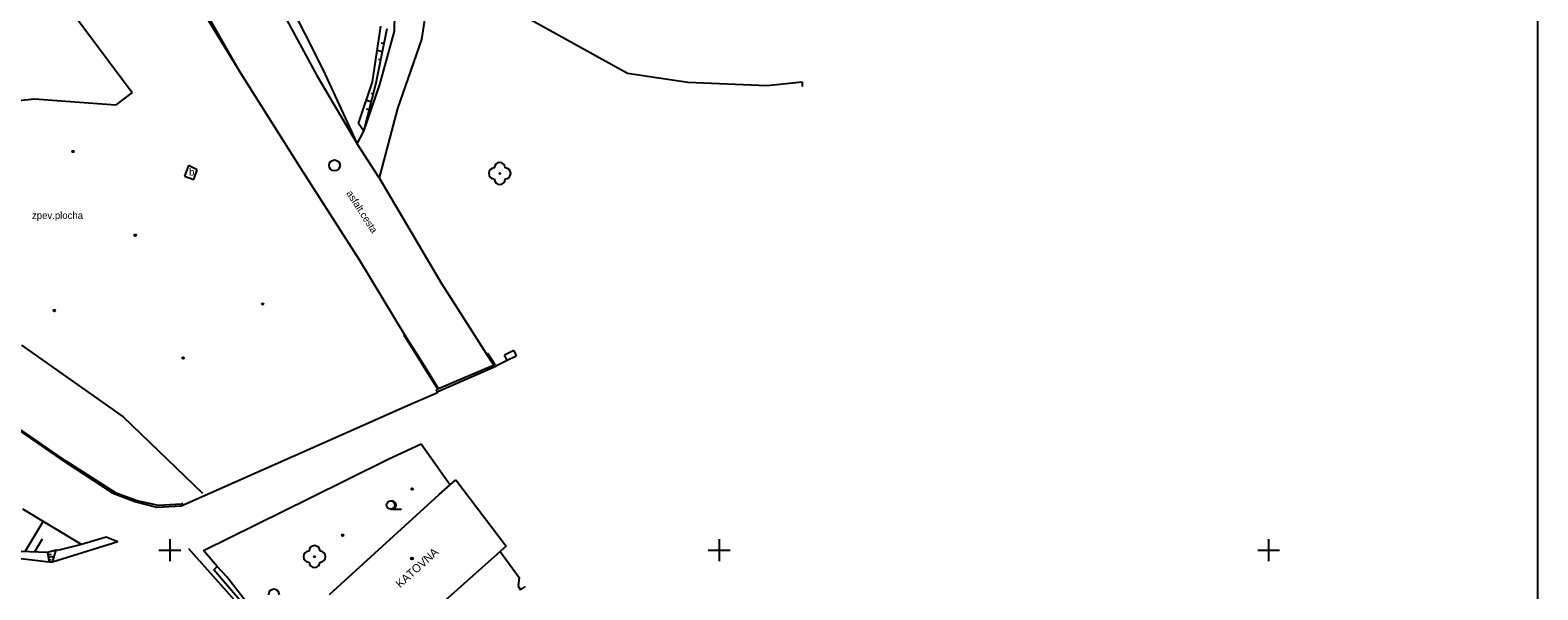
# Model space of a CAD drawing. Extents: x -639440 to -639026, y -1138850 to -1138262.
# Drawn here: x -639162.7 to -639025.5, y -1138653.6 to -1138602.7 of the extents above; entities that cross this region are included whole.
import ezdxf

# ---------------------------------------------------------------- set-up
doc = ezdxf.new("R2010")
doc.units = 0
for name, color, linetype in [('Vrstva 10', 7, 'Continuous'), ('Vrstva 11', 7, 'Continuous'), ('Vrstva 14', 7, 'Continuous'), ('Vrstva 15', 7, 'Continuous'), ('Vrstva 20', 7, 'Continuous'), ('Vrstva 22', 7, 'Continuous'), ('Vrstva 23', 7, 'Continuous'), ('Vrstva 27', 7, 'Continuous'), ('Vrstva 36', 7, 'Continuous'), ('Vrstva 39', 7, 'Continuous'), ('Vrstva 40', 7, 'Continuous'), ('Vrstva 41', 7, 'Continuous'), ('Vrstva 5', 7, 'Continuous'), ('Vrstva 60', 7, 'Continuous'), ('Vrstva 61', 7, 'Continuous'), ('Vrstva 7', 7, 'Continuous'), ('Vrstva 8', 7, 'Continuous')]:
    doc.layers.add(name, color=color, linetype=linetype)

msp = doc.modelspace()

# ---------------------------------------------------------------- linework, layer by layer
at = {"layer": 'Vrstva 10'}
for p, q in [((-639142.24, -1138596.43), (-639136.62, -1138606.78)), ((-639143.51, -1138606.64), (-639148.48, -1138597.96)), ((-639129.57, -1138602.75), (-639129.5, -1138599.47)), ((-639126.56, -1138599.96), (-639127.11, -1138603.5)), ((-639130.89, -1138607.61), (-639129.57, -1138602.75)), ((-639127.11, -1138603.5), (-639129.3, -1138609.79)), ((-639138.11, -1138615.21), (-639143.51, -1138606.64)), ((-639136.62, -1138606.78), (-639132.96, -1138613.01)), ((-639132.36, -1138611.87), (-639130.89, -1138607.61)), ((-639129.3, -1138609.79), (-639130.97, -1138616.1)), ((-639132.96, -1138613.01), (-639132.36, -1138611.87)), ((-639130.97, -1138616.1), (-639132.96, -1138613.01)), ((-639132.73, -1138623.64), (-639138.11, -1138615.21)), ((-639130.97, -1138616.1), (-639125.29, -1138625.72)), ((-639128.64, -1138630.36), (-639132.73, -1138623.64)), ((-639125.29, -1138625.72), (-639124.25, -1138627.32)), ((-639124.25, -1138627.32), (-639121.21, -1138632.1)), ((-639126.66, -1138633.52), (-639128.64, -1138630.36)), ((-639121.21, -1138632.1), (-639120.63, -1138632.97)), ((-639125.55, -1138635.32), (-639126.66, -1138633.52)), ((-639120.5, -1138633.16), (-639125.55, -1138635.32)), ((-639120.63, -1138632.97), (-639120.5, -1138633.16)), ((-639154.75, -1138649.25), (-639155.79, -1138648.83))]:
    msp.add_line(p, q, dxfattribs=at)
at = {"layer": 'Vrstva 11'}
for p, q in [((-639162, -1138596.86), (-639153.43, -1138608.35)), ((-639092.46, -1138607.38), (-639092.47, -1138607.8)), ((-639162.32, -1138608.96), (-639167.4, -1138609.48)), ((-639154.94, -1138609.49), (-639162.32, -1138608.96)), ((-639153.43, -1138608.35), (-639154.94, -1138609.49)), ((-639148.3, -1138614.99), (-639148.67, -1138615.95)), ((-639147.52, -1138615.37), (-639148.3, -1138614.99)), ((-639148.67, -1138615.95), (-639147.84, -1138616.25)), ((-639147.84, -1138616.25), (-639147.52, -1138615.37)), ((-639163.51, -1138631.34), (-639154.27, -1138637.86)), ((-639128.64, -1138630.36), (-639128.71, -1138630.41)), ((-639128.71, -1138630.41), (-639127.1, -1138632.97)), ((-639121.21, -1138632.1), (-639121.09, -1138632.06)), ((-639121.09, -1138632.06), (-639120.44, -1138633.09)), ((-639127.1, -1138632.97), (-639125.64, -1138635.32)), ((-639120.44, -1138633.09), (-639120.5, -1138633.16)), ((-639125.64, -1138635.32), (-639125.55, -1138635.32)), ((-639154.27, -1138637.86), (-639147.04, -1138644.82)), ((-639154.75, -1138649.25), (-639160.68, -1138651.1)), ((-639155.79, -1138648.83), (-639158.06, -1138649.5)), ((-639161, -1138651.09), (-639165.14, -1138650.62)), ((-639158.06, -1138649.5), (-639160.23, -1138650.04)), ((-639160.68, -1138651.1), (-639161, -1138651.09)), ((-639144.83, -1138652.44), (-639145.69, -1138651.48)), ((-639142.65, -1138655.24), (-639144.83, -1138652.44))]:
    msp.add_line(p, q, dxfattribs=at)
at = {"layer": 'Vrstva 14'}
for p, q in [((-639143.51, -1138606.64), (-639147.06, -1138600.83)), ((-639131.57, -1138607.38), (-639130.82, -1138602.31)), ((-639131.22, -1138607.47), (-639130.23, -1138602.51)), ((-639117.74, -1138601.4), (-639108.34, -1138606.57)), ((-639108.34, -1138606.57), (-639102.87, -1138607.4)), ((-639132.84, -1138611.17), (-639131.57, -1138607.38)), ((-639132.36, -1138611.87), (-639131.22, -1138607.47)), ((-639102.87, -1138607.4), (-639095.68, -1138607.7)), ((-639095.68, -1138607.7), (-639092.46, -1138607.38)), ((-639132.36, -1138611.87), (-639132.84, -1138611.17)), ((-639158.06, -1138649.5), (-639163.4, -1138646.27)), ((-639161.13, -1138650.22), (-639165.18, -1138650.05)), ((-639160.34, -1138650.01), (-639161.13, -1138650.22)), ((-639161.13, -1138650.22), (-639161, -1138651.09)), ((-639160.68, -1138651.1), (-639160.34, -1138650.01)), ((-639160.23, -1138650.04), (-639160.34, -1138650.01)), ((-639145.11, -1138652.81), (-639146, -1138651.8)), ((-639142.43, -1138655.97), (-639145.11, -1138652.81))]:
    msp.add_line(p, q, dxfattribs=at)
at = {"layer": 'Vrstva 15'}
for p, q in [((-639130.51, -1138603.89), (-639130.77, -1138603.84)), ((-639130.65, -1138604.63), (-639131.15, -1138604.53)), ((-639130.8, -1138605.36), (-639131.03, -1138605.32)), ((-639131.67, -1138609.2), (-639132.14, -1138609.08)), ((-639131.48, -1138608.48), (-639131.69, -1138608.42)), ((-639131.86, -1138609.93), (-639132.12, -1138609.86)), ((-639163.18, -1138650.13), (-639161.53, -1138647.4)), ((-639162.32, -1138650.17), (-639161.6, -1138648.98)), ((-639161.1, -1138650.42), (-639160.77, -1138650.37)), ((-639161.07, -1138650.65), (-639160.51, -1138650.56)), ((-639161.03, -1138650.87), (-639160.81, -1138650.84))]:
    msp.add_line(p, q, dxfattribs=at)
at = {"layer": 'Vrstva 20'}
for centre, radius in [((-639158.82, -1138613.71), 0.075), ((-639158.82, -1138613.71), 0.0204), ((-639153.16, -1138621.33), 0.075), ((-639153.16, -1138621.33), 0.0204), ((-639160.52, -1138628.19), 0.075), ((-639160.52, -1138628.19), 0.0204), ((-639141.56, -1138627.6), 0.075), ((-639141.56, -1138627.6), 0.0204), ((-639148.8, -1138632.51), 0.075), ((-639148.8, -1138632.51), 0.0204), ((-639127.95, -1138644.43), 0.075), ((-639127.95, -1138644.43), 0.0204), ((-639134.28, -1138648.64), 0.075), ((-639134.28, -1138648.64), 0.0204)]:
    msp.add_circle(centre, radius, dxfattribs=at)
at = {"layer": 'Vrstva 22'}
for centre in [(-639119.98, -1138615.71), (-639136.84, -1138650.59)]:
    msp.add_circle(centre, 0.05, dxfattribs=at)
for centre, start, end in [((-639119.98, -1138615.21), 0, 180), ((-639120.48, -1138615.71), 90, 270), ((-639119.98, -1138616.21), 180, 0), ((-639119.48, -1138615.71), 270, 90), ((-639137.34, -1138650.59), 90, 270), ((-639136.84, -1138650.09), 0, 180), ((-639136.34, -1138650.59), 270, 90), ((-639136.84, -1138651.09), 180, 0), ((-639140.54, -1138654.06), 0, 180)]:
    msp.add_arc(centre, 0.5, start, end, dxfattribs=at)
at = {"layer": 'Vrstva 23'}
for p, q in [((-639141.18, -1138596.13), (-639136.06, -1138606.3)), ((-639136.06, -1138606.3), (-639132.96, -1138613.01))]:
    msp.add_line(p, q, dxfattribs=at)
at = {"layer": 'Vrstva 27'}
msp.add_circle((-639135.02, -1138614.98), 0.5, dxfattribs=at)
at = {"layer": 'Vrstva 36'}
msp.add_line((-639129.91, -1138646.28), (-639128.91, -1138646.28), dxfattribs=at)
msp.add_circle((-639129.91, -1138645.9), 0.375, dxfattribs=at)
msp.add_arc((-639129.79, -1138645.9), 0.375, 260.4059, 99.5941, dxfattribs=at)
at = {"layer": 'Vrstva 39'}
for radius in [0.09, 0.0398]:
    msp.add_circle((-639127.97, -1138650.75), radius, dxfattribs=at)
at = {"layer": 'Vrstva 5'}
for p, q in [((-639125.51, -1138644.93), (-639123.98, -1138643.61)), ((-639123.98, -1138643.61), (-639119.41, -1138649.65)), ((-639135.49, -1138654.04), (-639125.51, -1138644.93)), ((-639119.93, -1138650.11), (-639124.94, -1138654.58)), ((-639119.41, -1138649.65), (-639119.93, -1138650.11))]:
    msp.add_line(p, q, dxfattribs=at)
at = {"layer": 'Vrstva 60'}
msp.add_lwpolyline([(-639440, -1138261.5), (-639440, -1138850), (-639025.5, -1138850), (-639025.5, -1138261.5)], close=True, dxfattribs=at)
at = {"layer": 'Vrstva 61'}
for p, q in [((-639150, -1138649), (-639150, -1138651)), ((-639100, -1138649), (-639100, -1138651)), ((-639050, -1138649), (-639050, -1138651)), ((-639151, -1138650), (-639149, -1138650)), ((-639101, -1138650), (-639099, -1138650)), ((-639051, -1138650), (-639049, -1138650))]:
    msp.add_line(p, q, dxfattribs=at)
at = {"layer": 'Vrstva 7'}
for p, q in [((-639119.31, -1138632.75), (-639120.34, -1138633.26)), ((-639118.69, -1138631.82), (-639119.56, -1138632.25)), ((-639119.31, -1138632.75), (-639119.56, -1138632.25)), ((-639118.54, -1138632.37), (-639119.31, -1138632.75)), ((-639118.69, -1138631.82), (-639118.48, -1138632.3)), ((-639118.48, -1138632.3), (-639118.54, -1138632.37)), ((-639125.66, -1138635.67), (-639128.58, -1138636.96)), ((-639125.79, -1138635.39), (-639125.66, -1138635.67)), ((-639159.61, -1138641.94), (-639168.55, -1138635.78)), ((-639159.45, -1138641.91), (-639168.33, -1138635.77)), ((-639128.58, -1138636.96), (-639131.11, -1138638.09)), ((-639131.11, -1138638.09), (-639148.99, -1138645.99)), ((-639130.19, -1138641.75), (-639127.14, -1138640.31)), ((-639127.14, -1138640.31), (-639124.48, -1138644.04)), ((-639155.1, -1138644.87), (-639159.61, -1138641.94)), ((-639154.9, -1138644.8), (-639159.45, -1138641.91)), ((-639137.29, -1138645.26), (-639130.19, -1138641.75)), ((-639153.2, -1138645.61), (-639155.1, -1138644.87)), ((-639152.97, -1138645.52), (-639154.9, -1138644.8)), ((-639144.55, -1138648.85), (-639137.29, -1138645.26)), ((-639151.18, -1138646.11), (-639153.2, -1138645.61)), ((-639151.03, -1138645.93), (-639152.97, -1138645.52)), ((-639148.99, -1138645.99), (-639151.18, -1138646.11)), ((-639148.96, -1138645.8), (-639151.03, -1138645.93)), ((-639148.87, -1138645.71), (-639148.96, -1138645.8)), ((-639146.93, -1138650.02), (-639144.55, -1138648.85)), ((-639148.31, -1138649.86), (-639142.65, -1138656.21)), ((-639145.69, -1138651.48), (-639146.93, -1138650.02)), ((-639119.93, -1138650.11), (-639118.22, -1138652.49)), ((-639146, -1138651.8), (-639145.69, -1138651.48)), ((-639118.22, -1138652.49), (-639118.31, -1138653.28)), ((-639118.31, -1138653.28), (-639118.1, -1138653.6)), ((-639118.1, -1138653.6), (-639117.64, -1138653.32))]:
    msp.add_line(p, q, dxfattribs=at)
at = {"layer": 'Vrstva 8'}
msp.add_line((-639125.63, -1138635.55), (-639120.34, -1138633.26), dxfattribs=at)

# ---------------------------------------------------------------- texts
at = {"layer": 'Vrstva 40'}
for s, p in [('b.', (-639148.26, -1138615.9)), ('zpev.plocha', (-639162.55, -1138619.85))]:
    msp.add_text(s, height=0.65, dxfattribs=at).set_placement(p)
msp.add_text('asfalt.cesta', height=0.65, rotation=302.5459, dxfattribs=at).set_placement((-639133.97, -1138617.51))
at = {"layer": 'Vrstva 41'}
msp.add_text('KATOVNA', height=0.75, rotation=42.1819, dxfattribs=at).set_placement((-639129.04, -1138653.49))

doc.saveas('drawing.dxf')
